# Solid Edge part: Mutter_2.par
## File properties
Dokumentum tartalom típus: 0
Last saved by: ahadarics
Revision: 76
Sűrűség: 0,000 kg/m^3
Pontosság: 0,990
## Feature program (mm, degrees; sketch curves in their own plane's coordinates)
base feature "unnamed BaseFeature 1"
thread "unnamed Thread 1"
chamfer "unnamed Chamfer 1"
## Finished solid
Body 1: solid body, 13 faces, 24 edges, 12 vertices.
  Faces by surface: plane 8, cone 4, cylinder 1
  Edges by curve: spline 12, circle 6, line 6
Bounding box of the edges (mm): 31.177 x 27.000 x 8.000, from (-15.5885, -13.5, -4) to (15.5885, 13.5, 4).
Cylindrical faces by radius (mm): R10.188 x1
Conical faces (half-angle, radius in mm at the cone's reference point): 45 deg R10.188 x1, 45 deg R11.188 x1, 75 deg R14.5 x2
Planar faces by outward normal: +y 1, +z 1, -y 1, -z 1, oblique 4
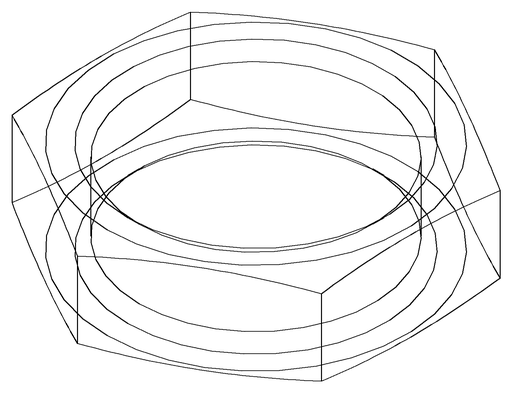
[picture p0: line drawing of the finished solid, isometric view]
